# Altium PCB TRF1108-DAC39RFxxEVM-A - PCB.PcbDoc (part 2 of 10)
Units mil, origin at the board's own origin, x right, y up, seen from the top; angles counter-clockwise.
Board outline 4951.22 x 2726.56 mil, 16 copper layers (Top Layer, L2 GND1, L3 PWR1, L4 GND2, L5 PWR2, L6 GND3, L7 Ctrl Signal 1, L8 GND4, L9 GND5, L10 Ctrl Signal 2, L11 GND6, L12 PWR3, L13 GND7, L14 PWR4, L15 GND8, Bottom Layer), stack 80.2 mil thick; 705 components, 433 nets, 3633 pads, 1678 vias.
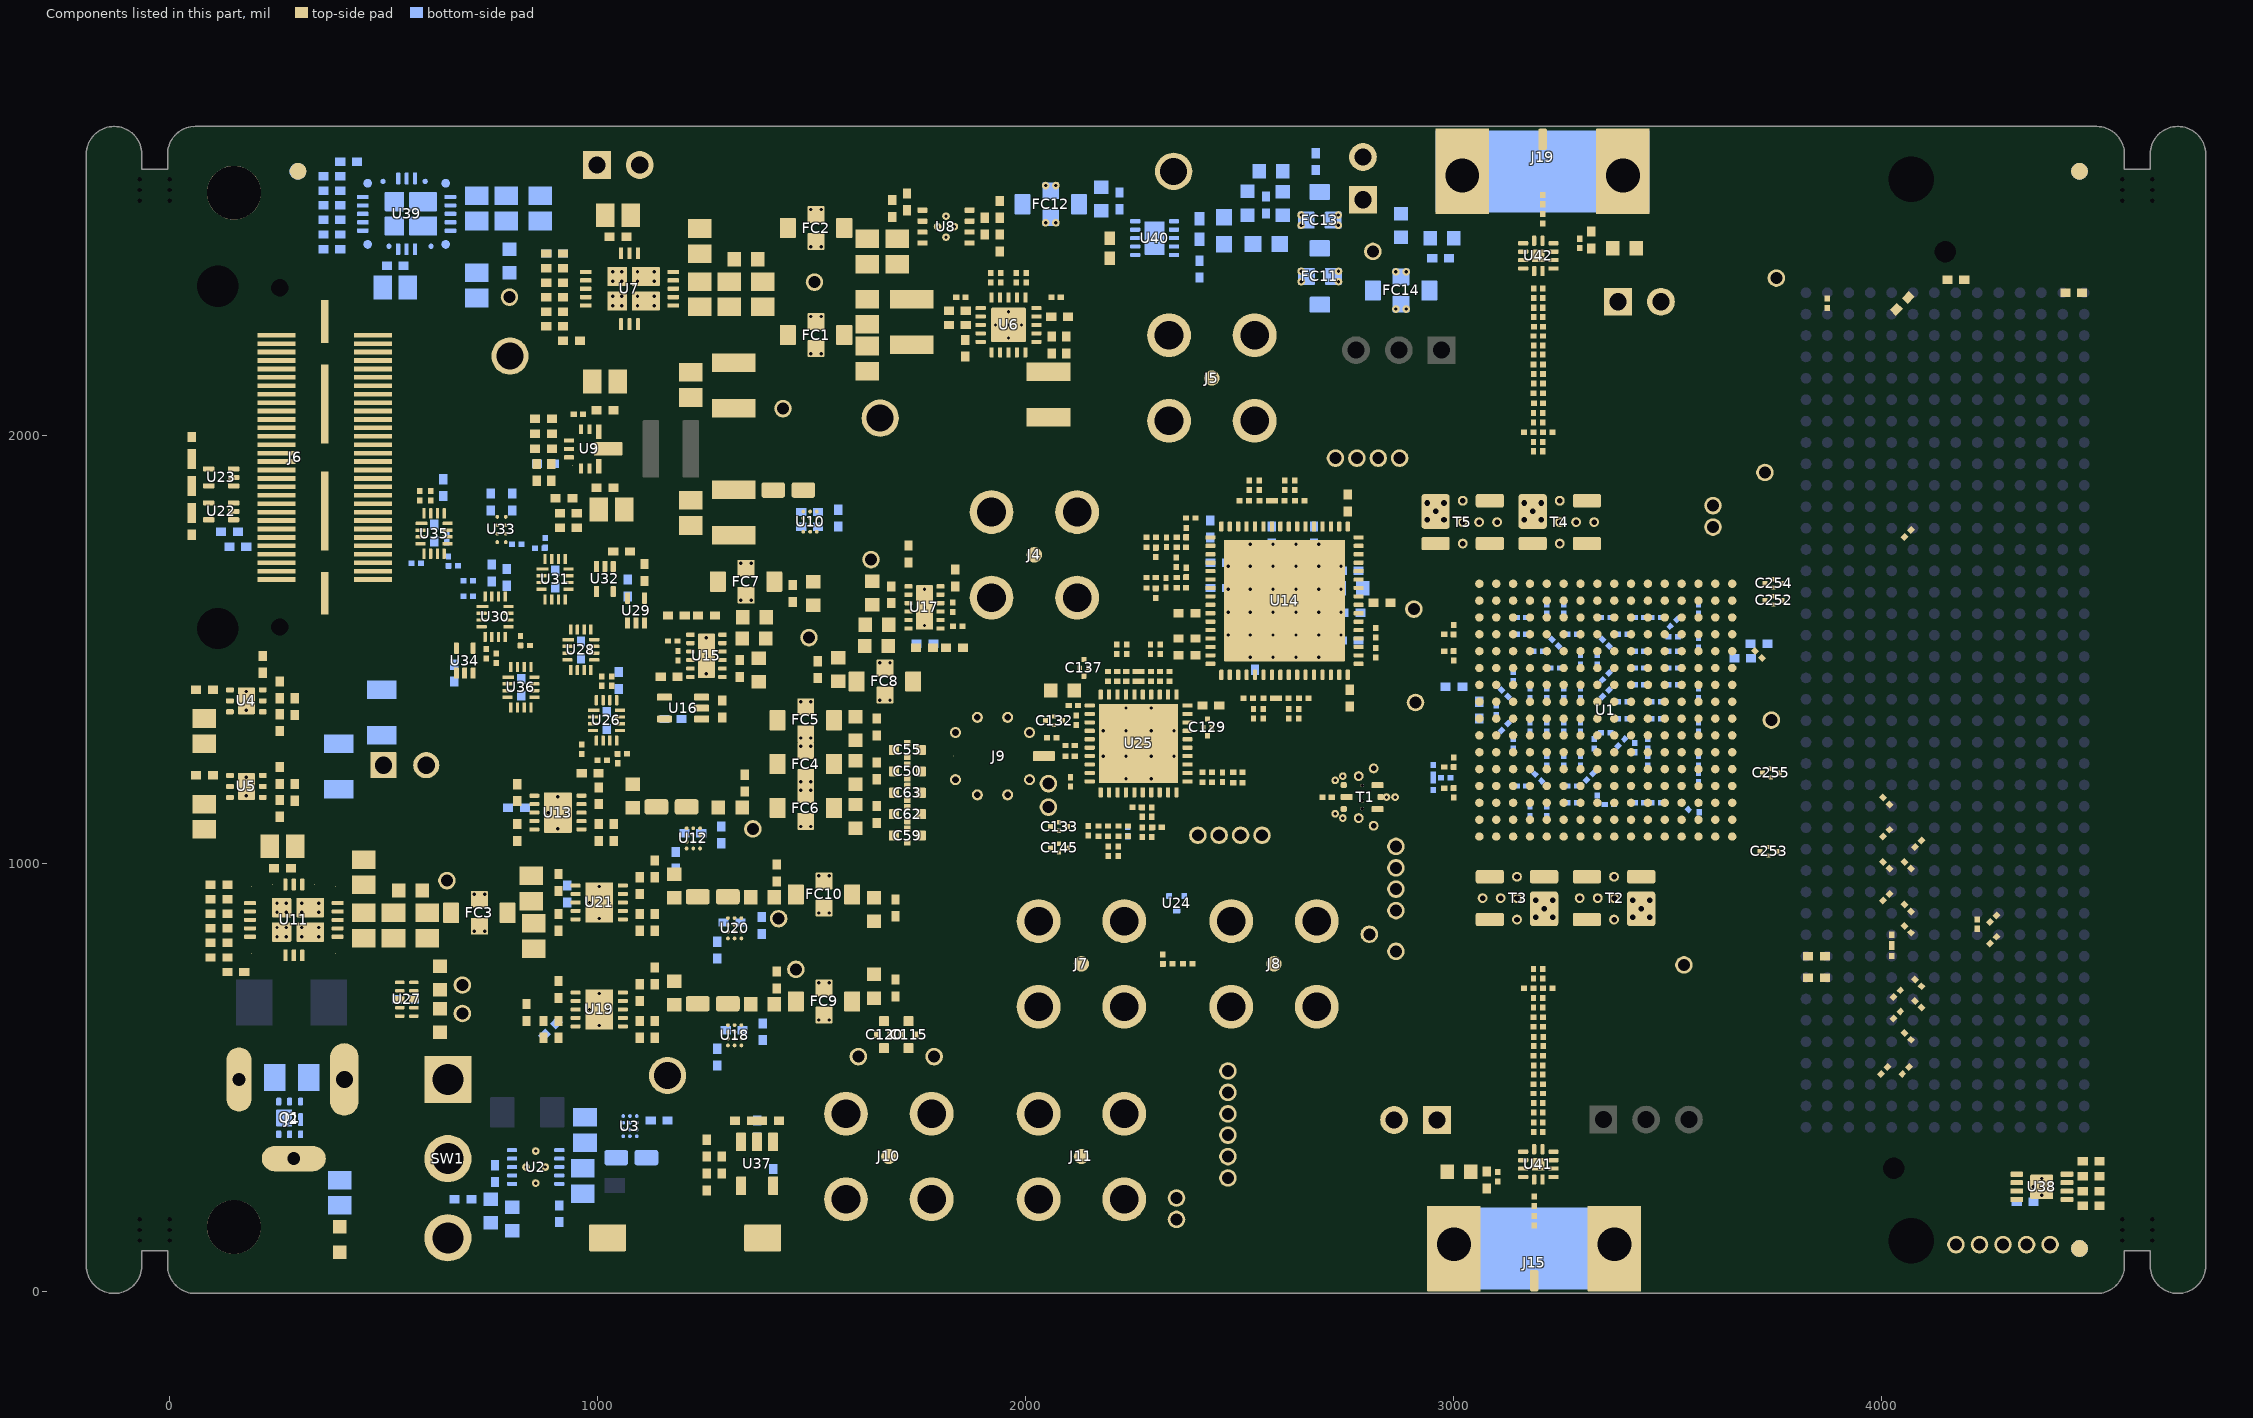
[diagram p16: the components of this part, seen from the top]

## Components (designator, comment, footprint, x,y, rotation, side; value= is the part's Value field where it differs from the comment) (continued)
PP37 "Probe Point" ProbePoint_TH_40mil 2864.85,939.47 r0 top
PP38 "Probe Point" ProbePoint_TH_40mil 2864.85,889.47 r0 top
PP39 "Probe Point" ProbePoint_TH_40mil 3537.64,762.6 r90 top
PP40 "Probe Point" ProbePoint_TH_40mil 3726.83,1913.06 r90 top
PP41 "Probe Point" ProbePoint_TH_40mil 2864.85,794.47 r0 top
PP42 "Probe Point" ProbePoint_TH_40mil 4338.12,109 r90 top
PP43 "Probe Point" ProbePoint_TH_40mil 4283.12,109 r90 top
PP44 "Probe Point" ProbePoint_TH_40mil 4228.12,109 r90 top
PP45 "Probe Point" ProbePoint_TH_40mil 4173.12,109 r90 top
PP46 "Probe Point" ProbePoint_TH_40mil 2352.17,218 r0 top
PP47 "Probe Point" ProbePoint_TH_40mil 2352.17,168 r0 top
PP48 "Probe Point" ProbePoint_TH_40mil 3753.4,2367.25 r0 top
PP49 "Probe Point" ProbePoint_TH_40mil 4393.12,109 r90 top
PP50 "Probe Point" ProbePoint_TH_40mil 793.81,2322.63 r0 bottom
PP51 "Probe Point" ProbePoint_TH_40mil 2810.83,2429.53 r90 top
Q1 "CSD15571Q2" DQK0006C 280.32,405.04 r270 bottom value=20V
R1 "CSS0603FT2L00" CCS0603FLxLxx 1078.28,312.22 r180 bottom value="2 mΩ"
R2 "ERJ-2RKF1004X" 0402L 760,274.77 r90 bottom value="1 MΩ"
R3 "ERJ-2RKF4532X" 0402L 910.24,181.26 r90 bottom value="45.3 kΩ"
R4 "ERJ-2GEJ472X" 0402L 685.43,215 r0 bottom value="4.7 kΩ"
R5 "ERJ-6ENF2201V" 0805L 397.23,230.16 r270 bottom value="2.2 kΩ"
R6 "RCA12060000ZSEA" 1206L 395.4,1226.06 r270 bottom value="0 Ω"
R7 "RCA12060000ZSEA" 1206L 495.4,1352.36 r90 bottom value="0 Ω"
R8 "ERJ-2GEJ472X" 0402L 217.6,1464.88 r90 top value="4.7 kΩ"
R9 "ERJ-2GEJ472X" 0402L 81.15,1405.2 r180 top value="4.7 kΩ"
R10 "ERJ-2GEJ205X" 0402L 292.6,1365.83 r270 top value="2 MΩ"
R11 "ERJ-2GEJ472X" 0402L 81.15,1205.2 r180 top value="4.7 kΩ"
R12 "ERJ-2GEJ365X" 0402L 292.6,1165.83 r270 top value="3.6 MΩ"
R13 "ERJ-2GEJ125X" 0402L 257.6,1405.2 r270 top value="1.2 MΩ"
R14 "ERJ-2GEJ125X" 0402L 257.6,1205.2 r270 top value="1.2 MΩ"
R15 "ERJ-2GEJ472X" 0402L 2079.32,2277.36 r0 top value="4.7 kΩ"
R16 "ERJ-2GEJ104X" 0402L 1840.03,2291.36 r180 top value="100 kΩ"
R17 "ERJ-2GEJ472X" 0402L 1858.91,2203.31 r270 top value="4.7 kΩ"
R18 "ERJ-2GE0R00X" 0402L 2060.43,2211.15 r270 top value="0 Ω"
R19 "ERJ-1GN0R00C" 0201 1848.69,2322.05 r0 top value="0 Ω"
R20 "ERJ-2GEJ472X" 0402L 899.32,2424.63 r180 top value="4.7 kΩ"
R21 "ERJ-1GN0R00C" 0201 1918.3,2367.68 r270 top value="0 Ω"
R22 "ERJ-1GN0R00C" 0201 1941.99,2367.68 r270 top value="0 Ω"
R23 "ERJ-1GN0R00C" 0201 1977.36,2367.68 r270 top value="0 Ω"
R24 "ERJ-1GN0R00C" 0201 2001.04,2367.68 r270 top value="0 Ω"
R25 "ERJ-2GEJ472X" 0402L 899.32,2254.63 r180 top value="4.7 kΩ"
R26 "ERJ-1GN0R00C" 0201 2070.66,2322.05 r180 top value="0 Ω"
R27 "ERJ-2RKF1822X" 0402L 899.32,2356.63 r180 top value="18.2 kΩ"
R28 "ERJ-2GEJ472X" 0402L 938.69,2220.63 r180 top value="4.7 kΩ"
R29 "ERJ-2RKF1822X" 0402L 899.32,2288.63 r0 top value="18.2 kΩ"
R30 "ERJ-2RKF4871X" 0402L 899.32,2322.63 r0 top value="4.87 kΩ"
R31 "ERJ-2GEJ472X" 0402L 1722.49,2545.47 r90 top value="4.7 kΩ"
R32 "ERJ-2RKF3092X" 0402L 1904.53,2488.58 r270 top value="30.9 kΩ"
R33 "ERJ-H2RF1002X" 0402L 1939.53,2527.95 r270 top value="10 kΩ"
R34 "ERJ-2GEJ472X" 0402L 873.22,1968.19 r180 top value="4.7 kΩ"
R35 "ERJ-2GEJ472X" 0402L 931.27,1817.43 r180 top value="4.7 kΩ"
R36 "CSS0603FT2L00" CCS0603FLxLxx 1444.92,1871.8 r180 top value="2 mΩ"
R37 "ERJ-2GE0R00X" 0402L 1495.04,1786.68 r180 bottom value="0 Ω"
R38 "ERJ-2GE0R00X" 0402L 1495.04,1820.68 r180 bottom value="0 Ω"
R39 "ERJ-2GEJ472X" 0402L 931.27,1783.43 r0 top value="4.7 kΩ"
R40 "ERJ-H2RF1002X" 0402L 857.91,1913.5 r270 top value="10 kΩ"
R41 "ERJ-2RKF4871X" 0402L 873.22,2003.19 r0 top value="4.87 kΩ"
R42 "ERJ-2RKF1742X" 0402L 873.22,2038.19 r0 top value="17.4 kΩ"
R43 "ERJ-2GE0R00X" 0402L 877.59,1933.19 r0 bottom value="0 Ω"
R44 "ERJ-H2RF1002X" 0402L 891.91,1913.5 r90 top value="10 kΩ"
R45 "ERJ-H2RF1002X" 0402L 3713.03,1512.58 r0 bottom value="10 kΩ"
R46 "ERJ-1GN0R00C" 0201 3711.83,1487.79 r135 top value="0 Ω"
R47 "ERJ-H2RF1002X" 0402L 3675.04,1478.58 r0 bottom value="10 kΩ"
R48 "ERJ-2GEJ472X" 0402L 115.08,949.98 r180 top value="4.7 kΩ"
R49 "ERJ-2GEJ472X" 0402L 115.08,779.98 r180 top value="4.7 kΩ"
R50 "ERJ-2RKF9311X" 0402L 115.08,881.98 r180 top value="9.31 kΩ"
R51 "ERJ-2GEJ472X" 0402L 154.45,745.98 r180 top value="4.7 kΩ"
R52 "ERJ-2RKF5232X" 0402L 115.08,813.98 r0 top value="52.3 kΩ"
R53 "ERJ-2RKF4871X" 0402L 115.08,847.98 r0 top value="4.87 kΩ"
R54 "ERJ-2GE0R00X" 0402L 1182.58,1007.04 r90 bottom value="0 Ω"
R55 "ERJ-2GE0R00X" 0402L 1222.26,1069.73 r180 bottom value="0 Ω"
R56 "ERJ-H2RF1002X" 0402L 811.87,1072.01 r270 top value="10 kΩ"
R57 "CSS0603FT2L00" CCS0603FLxLxx 1172.15,1131.85 r180 top value="2 mΩ"
R58 "ERJ-2GEJ472X" 0402L 810.32,1130 r180 bottom value="4.7 kΩ"
R59 "ERJ-2RKF8872X" 0402L 1002.11,1157.83 r270 top value="88.7 kΩ"
R60 "ERJ-2RKF1242X" 0402L 982.42,1210.55 r0 top value="12.4 kΩ"
R61 "ERJ-U2RD1202X" 0402L 1002.11,1072.01 r90 top value="12 kΩ"
R62 "ERJ-1GNF49R9C" 0201 2351.78,1703.45 r270 top value="49.9 Ω"
R63 "ERJ-1GN0R00C" 0201 2292.66,1667.59 r0 top value="0 Ω"
R64 "ERJ-1GNF1000C" 0201 2327.69,1655.73 r90 top value="100 Ω"
R65 "ERJ-1GN0R00C" 0201 2292.66,1643.12 r0 top value="0 Ω"
R66 "ERJ-1GNF49R9C" 0201 2303.69,1631.31 r90 top value="49.9 Ω"
R67 "ERJ-1GNF49R9C" 0201 2385.76,1806.69 r180 top value="49.9 Ω"
R68 "ERJ-1GN0R00C" 0201 2292.76,1761.65 r0 top value="0 Ω"
R69 "ERJ-1GNF1000C" 0201 2328.79,1749.78 r90 top value="100 Ω"
R70 "ERJ-1GN0R00C" 0201 2292.76,1737.96 r0 top value="0 Ω"
R71 "ERJ-1GNF49R9C" 0201 2303.79,1726.15 r90 top value="49.9 Ω"
R72 "ERJ-1GNF1200C" 0201 2817.76,1491.9 r90 top value="120 Ω"
R73 "ERJ-1GNF1200C" 0201 2817.76,1538.63 r270 top value="120 Ω"
R74 "ERJ-1GNF1200C" 0201 2520.16,1385.46 r0 top value="120 Ω"
R75 "ERJ-1GNF1200C" 0201 2566.74,1385.46 r180 top value="120 Ω"
R76 "ERJ-1GNF1200C" 0201 2602.96,1385.46 r0 top value="120 Ω"
R77 "ERJ-1GNF1200C" 0201 2649.53,1385.46 r180 top value="120 Ω"
R78 "ERJ-1GNF1200C" 0201 2639.92,1846.92 r180 top value="120 Ω"
R79 "ERJ-1GNF1200C" 0201 2593.11,1846.92 r0 top value="120 Ω"
R80 "ERJ-1GNF1200C" 0201 2556.89,1846.92 r180 top value="120 Ω"
R81 "ERJ-1GNF1200C" 0201 2510.09,1846.92 r0 top value="120 Ω"
R82 "ERJ-H2RF1002X" 0402L 2758.02,1520.52 r0 bottom value="10 kΩ"
R83 "ERJ-H2RF1002X" 0402L 2761.92,1585.21 r0 bottom value="10 kΩ"
R84 "ERJ-2GEJ472X" 0402L 1291.37,1360.2 r270 top value="4.7 kΩ"
R85 "ERJ-2RKF2553X" 0402L 1253.96,1578.94 r0 top value="255 kΩ"
R86 "ERJ-2GEJ472X" 0402L 1166.88,1435.51 r0 top value="4.7 kΩ"
R87 "ERJ-2RKF4993X" 0402L 1183.59,1578.94 r0 top value="499 kΩ"
R88 "ERJ-2GEJ472X" 0402L 1725.98,1722.42 r90 top value="4.7 kΩ"
R89 "ERJ-2GEJ472X" 0402L 1764.69,1512.73 r180 bottom value="4.7 kΩ"
R90 "ERJ-2RKF2553X" 0402L 1763.39,1503.68 r180 top value="255 kΩ"
R91 "ERJ-2GEJ472X" 0402L 1834.79,1666.79 r270 top value="4.7 kΩ"
R92 "ERJ-2RKF4993X" 0402L 1833.76,1503.68 r180 top value="499 kΩ"
R93 "ERJ-2GE0R00X" 0402L 1279.08,547.04 r90 bottom value="0 Ω"
R94 "ERJ-2GE0R00X" 0402L 1318.76,609.73 r180 bottom value="0 Ω"
R95 "ERJ-H2RF1002X" 0402L 908.37,612.01 r270 top value="10 kΩ"
R96 "CSS0603FT20L0" CCS0603FLxLxx 1268.65,671.85 r180 top value="20 mΩ"
R97 "ERJ-2GEJ472X" 0402L 833.53,651.38 r90 top value="4.7 kΩ"
R98 "ERJ-2RKF1153X" 0402L 1098.61,697.83 r270 top value="115 kΩ"
R99 "ERJ-2RKF3302X" 0402L 1133.61,737.2 r270 top value="33 kΩ"
R100 "ERJ-2RKF6651X" 0402L 1098.61,612.01 r90 top value="6.65 kΩ"
R101 "ERJ-2GE0R00X" 0402L 1279.08,797.04 r90 bottom value="0 Ω"
R102 "ERJ-2GE0R00X" 0402L 1313.76,861.73 r180 bottom value="0 Ω"
R103 "ERJ-2GE0R00X" 0402L 873.37,612.01 r90 top value="0 Ω"
R104 "ERJ-H2RF1002X" 0402L 908.37,862.01 r270 top value="10 kΩ"
R105 "CSS0603FT20L0" CCS0603FLxLxx 1268.65,921.85 r180 top value="20 mΩ"
R106 "ERJ-2GEJ472X" 0402L 928.37,928.15 r90 bottom value="4.7 kΩ"
R107 "ERJ-2GE0R00X" 0402L 889.45,612.77 r225 bottom value="0 Ω"
R108 "ERJ-2RKF1153X" 0402L 1098.61,947.83 r270 top value="115 kΩ"
R109 "ERJ-2RKF3302X" 0402L 1133.61,987.2 r270 top value="33 kΩ"
R110 "ERJ-2RKF6651X" 0402L 1098.61,862.01 r90 top value="6.65 kΩ"
R111 "ERJ-2GEJ472X" 0402L 139.69,1775 r180 bottom value="4.7 kΩ"
R112 "ERJ-2GEJ472X" 0402L 51.14,1850.18 r270 top value="4.7 kΩ"
R113 "ERJ-2GE0R00X" 0402L 51.14,1787.31 r270 top value="0 Ω"
R114 "ERJ-2GEJ472X" 0402L 159.11,1740 r0 bottom value="4.7 kΩ"
R115 "ERJ-2GEJ472X" 0402L 51.14,1913.05 r90 top value="4.7 kΩ"
R116 "ERJ-2GE0R00X" 0402L 51.14,1975.92 r90 top value="0 Ω"
R117 "ERJ-1GNF66R5C" 0201 2952,1218.42 r90 bottom value="66.5 Ω"
R118 "ERJ-1GNF66R5C" 0201 2952,1182.2 r90 bottom value="66.5 Ω"
R119 "ERJ-1GN0R00C" 0201 2423.78,1189.41 r0 top value="0 Ω"
R120 "ERJ-1GN0R00C" 0201 2271.75,1072.75 r90 top value="0 Ω"
R121 "ERJ-1GN0R00C" 0201 2423.78,1213.09 r0 top value="0 Ω"
R122 "ERJ-1GNF1000C" 0201 2459.74,1201.25 r90 top value="100 Ω"
R123 "ERJ-1GNF1000C" 0201 2118,1334 r270 top value="100 Ω"
R124 "ERJ-1GN0R00C" 0201 2294.8,1072.75 r90 top value="0 Ω"
R125 "ERJ-1GNF49R9C" 0201 2306.61,1083.77 r180 top value="49.9 Ω"
R126 "ERJ-1GNF49R9C" 0201 2060.34,1293.15 r0 top value="49.9 Ω"
R127 "ERJ-1GNF82R5C" 0201 2181.42,1087.18 r180 top value="82.5 Ω"
R128 "ERJ-1GNF1000C" 0201 2104.41,1190.07 r270 top value="100 Ω"
R129 "ERJ-1GNF49R9C" 0201 2202.7,1448.17 r0 top value="49.9 Ω"
R130 "ERJ-1GNF49R9C" 0201 2245.73,1448.17 r180 top value="49.9 Ω"
R131 "ERJ-1GNF49R9C" 0201 2281.44,1448.17 r0 top value="49.9 Ω"
R132 "ERJ-1GNF49R9C" 0201 2324.47,1448.17 r180 top value="49.9 Ω"
R133 "ERJ-1GN0R00C" 0201 2193.01,1028.16 r90 top value="0 Ω"
R134 "ERJ-1GNF1300C" 0201 2181.42,1063.18 r0 top value="130 Ω"
R135 "ERJ-1GNF82R5C" 0201 2227.64,1087.18 r0 top value="82.5 Ω"
R136 "ERJ-1GN0R00C" 0201 2216.06,1028.16 r90 top value="0 Ω"
R137 "ERJ-1GNF1300C" 0201 2227.64,1063.18 r180 top value="130 Ω"
R138 "ERJ-1GNF49R9C" 0201 2202.7,1425.17 r180 top value="49.9 Ω"
R139 "ERJ-1GNF49R9C" 0201 2245.73,1425.17 r0 top value="49.9 Ω"
R140 "ERJ-1GNF49R9C" 0201 2281.44,1425.17 r180 top value="49.9 Ω"
R141 "ERJ-1GNF49R9C" 0201 2324.47,1425.17 r0 top value="49.9 Ω"
R142 "ERJ-1GN0R00C" 0201 1032.8,1425.8 r270 top value="0 Ω"
R143 "ERJ-1GN0R00C" 0201 1009.23,1425.8 r270 top value="0 Ω"
R144 "ERJ-1GN0R00C" 0201 962.74,1266.32 r90 top value="0 Ω"
R145 "ERJ-1GN0R00C" 0201 1010.18,1241.1 r0 top value="0 Ω"
R146 "ERJ-1GN0R00C" 0201 1057.44,1255.72 r0 top value="0 Ω"
R147 "ERJ-1GN0R00C" 0201 1046.42,1244.7 r90 top value="0 Ω"
R148 "ERJ-3GEYJ222V" 0603L 631.56,731.88 r270 top value="2.2 kΩ"
R149 "ERJ-3GEYJ222V" 0603L 631.56,632.77 r90 top value="2.2 kΩ"
R150 "ERJ-2GEJ472X" 0402L 1109.21,1679.17 r90 top value="4.7 kΩ"
R151 "ERJ-2GEJ472X" 0402L 1069.84,1643.19 r90 bottom value="4.7 kΩ"
R152 "ERJ-1GN0R00C" 0201 697.93,1659.91 r0 bottom value="0 Ω"
R153 "ERJ-1GN0R00C" 0201 697.93,1624.17 r0 bottom value="0 Ω"
R154 "ERJ-1GN0R00C" 0201 739.82,1489.65 r270 top value="0 Ω"
R155 "ERJ-1GN0R00C" 0201 762.82,1478.65 r270 top value="0 Ω"
R156 "ERJ-2GEJ472X" 0402L 1056,1728.44 r180 top value="4.7 kΩ"
R157 "ERJ-1GN0R00C" 0201 830.69,1508.72 r0 top value="0 Ω"
R158 "ERJ-1GN0R00C" 0201 819.67,1519.75 r270 top value="0 Ω"
R159 "ERJ-1GN0R00C" 0201 864.55,1736.04 r180 bottom value="0 Ω"
R160 "ERJ-1GN0R00C" 0201 811.05,1745.36 r0 bottom value="0 Ω"
R161 "ERJ-2GEJ472X" 0402L 899.32,2424.63 r180 bottom value="4.7 kΩ"
R162 "ERJ-1GN0R00C" 0201 877.57,1749.06 r270 bottom value="0 Ω"
R163 "ERJ-2GEJ472X" 0402L 664.58,1444.09 r270 bottom value="4.7 kΩ"
R164 "ERJ-1GN0R00C" 0201 609.82,1858.69 r270 top value="0 Ω"
R165 "ERJ-1GN0R00C" 0201 584.08,1858.69 r90 top value="0 Ω"
R166 "ERJ-1GN0R00C" 0201 647,1761.02 r270 bottom value="0 Ω"
R167 "ERJ-1GN0R00C" 0201 576.14,1701.27 r0 bottom value="0 Ω"
R168 "ERJ-1GN0R00C" 0201 662.34,1694.97 r0 bottom value="0 Ω"
R169 "ERJ-1GN0R00C" 0201 651.32,1705.99 r270 bottom value="0 Ω"
R170 "ERJ-2GEJ104X" 0402L 1254.63,334.41 r90 top value="100 kΩ"
R171 "ERJ-2GE0R00X" 0402L 1289.63,295.04 r270 top value="0 Ω"
R172 "ERJ-2GE0R00X" 0402L 1254.63,255.67 r270 top value="0 Ω"
R173 "ERJ-2GE0R00X" 0402L 1403.72,398.96 r0 top value="0 Ω"
R174 "ERJ-2GE0R00X" 0402L 1340.73,398.96 r180 top value="0 Ω"
R175 "ERJ-1GN0R00C" 0201 3453.51,1239.68 r270 bottom value="0 Ω"
R176 "ERJ-2RKF1001X" 0402L 3000.75,1412.79 r180 bottom value="1 kΩ"
R177 "ERJ-2RKF3601X" 0402L 3059.81,1357.79 r90 bottom value="3.6 kΩ"
R178 "ERJ-2GEJ472X" 0402L 378.68,2604.99 r180 bottom value="4.7 kΩ"
R179 "CRCW040228K7FKED" 0402L 378.68,2502.99 r0 bottom value=28.7k
R180 "ERJ-2RKF4871X" 0402L 378.68,2536.99 r0 bottom value="4.87 kΩ"
R181 "ERJ-2GEJ472X" 0402L 418.05,2638.99 r180 bottom value="4.7 kΩ"
R182 "ERJ-2RKF1822X" 0402L 378.68,2570.99 r0 bottom value="18.2 kΩ"
R183 "ERJ-2GEJ472X" 0402L 378.68,2434.99 r180 bottom value="4.7 kΩ"
R184 "RC0603FR-0710K5L" 0603 2462.67,2477.9 r90 bottom value=10.5k
R185 "RC0603FR-072KL" 0603 2562.03,2446.9 r0 bottom value=2.00k
R186 "ERJ-1GN0R00C" 0201 3187.76,164.84 r270 top value="0 Ω"
R187 "ERJ-1GN0R00C" 0201 3207.44,2550.73 r90 top value="0 Ω"
R189 "ERJ-2GEJ472X" 0402L 2405.95,2388.04 r270 bottom value="4.7 kΩ"
R192 "ERJ-1GNF1400C" 0201 3219.26,708.12 r0 top value="140 Ω"
R196 "RC0201FR-078R66L" 0201 3208.23,741.92 r270 top value="8.66 Ω"
R197 "RC0201FR-078R66L" 0201 3208.23,674.31 r270 top value="8.66 Ω"
R200 "ERJ-1GN0R00C" 0201 3208.23,383.47 r270 top value="0 Ω"
R201 "RC0201FR-078R66L" 0201 3186.18,741.92 r270 top value="8.66 Ω"
R202 "RC0201FR-078R66L" 0201 3186.18,674.31 r270 top value="8.66 Ω"
R204 "ERJ-2GE0R00X" 0402L 4172.81,2363.06 r0 top value="0 Ω"
R205 "ERJ-1GN0R00C" 0201 4260.31,870.56 r45 top value="0 Ω"
R206 "ERJ-1GN0R00C" 0201 4222.81,858.06 r90 top value="0 Ω"
R207 "ERJ-1GN0R00C" 0201 4260.31,820.56 r45 top value="0 Ω"
R208 "ERJ-2GEJ101X" 0402L 4047.78,2308.02 r225 top value="100 Ω"
R209 "ERJ-1GN0R00C" 0201 4060.31,1770.56 r45 top value="0 Ω"
R210 "ERJ-2GEJ472X" 0402L 4489.17,303.88 r0 top value="4.7 kΩ"
R211 "ERJ-1GN0R00C" 0201 4010.31,1145.55 r315 top value="0 Ω"
R212 "ERJ-1GN0R00C" 0201 4010.31,1070.56 r45 top value="0 Ω"
R213 "ERJ-2GEJ472X" 0402L 4489.17,199.51 r180 top value="4.7 kΩ"
R214 "ERJ-2GEJ472X" 0402L 4489.17,234.2 r180 top value="4.7 kΩ"
R215 "ERJ-2GEJ472X" 0402L 4489.17,268.88 r180 top value="4.7 kΩ"
R216 "ERJ-1GN0R00C" 0201 4085.31,1045.56 r225 top value="0 Ω"
R217 "ERJ-1GN0R00C" 0201 4010.31,995.56 r315 top value="0 Ω"
R218 "ERJ-1GN0R00C" 0201 4060.31,995.56 r315 top value="0 Ω"
R219 "ERJ-1GN0R00C" 0201 4010.31,920.56 r45 top value="0 Ω"
R220 "ERJ-1GN0R00C" 0201 4060.31,895.56 r315 top value="0 Ω"
R221 "ERJ-1GN0R00C" 0201 4022.81,822.03 r90 top value="0 Ω"
R222 "ERJ-1GN0R00C" 0201 4060.31,845.56 r315 top value="0 Ω"
R223 "ERJ-1GN0R00C" 0201 4022.81,794.08 r270 top value="0 Ω"
R224 "ERJ-1GN0R00C" 0201 4085.31,720.56 r135 top value="0 Ω"
R225 "ERJ-1GN0R00C" 0201 4035.33,695.56 r225 top value="0 Ω"
R226 "ERJ-1GN0R00C" 0201 4085.31,670.56 r135 top value="0 Ω"
R227 "ERJ-1GN0R00C" 0201 4035.31,645.56 r225 top value="0 Ω"
R228 "ERJ-1GN0R00C" 0201 4060.31,595.56 r315 top value="0 Ω"
R229 "ERJ-1GN0R00C" 0201 4005.61,515.85 r45 top value="0 Ω"
R230 "ERJ-1GN0R00C" 0201 4055.61,515.85 r45 top value="0 Ω"
R231 "ERJ-1GN0R00C" 0201 3872.81,2308.06 r90 top value="0 Ω"
R232 "ERJ-2GEJ101X" 0402L 3847.22,783.06 r0 top value="100 Ω"
R233 "ERJ-2GEJ101X" 0402L 3847.22,733.06 r0 top value="100 Ω"
R234 "ERJ-2GEJ101X" 0402L 4448.4,2333.06 r180 top value="100 Ω"
R236 "ERJ-1GN0R00C" 0201 3186.97,383.47 r270 top value="0 Ω"
R237 "ERJ-1GNF1400C" 0201 3175.16,708.12 r0 top value="140 Ω"
R242 "ERJ-1GNF1400C" 0201 3219.26,2007.46 r0 top value="140 Ω"
R246 "RC0201FR-078R66L" 0201 3208.23,1973.66 r90 top value="8.66 Ω"
R247 "RC0201FR-078R66L" 0201 3208.23,2041.26 r90 top value="8.66 Ω"
R250 "ERJ-1GN0R00C" 0201 3208.23,2332.1 r90 top value="0 Ω"
R251 "RC0201FR-078R66L" 0201 3186.18,1973.66 r90 top value="8.66 Ω"
R252 "RC0201FR-078R66L" 0201 3186.18,2041.26 r90 top value="8.66 Ω"
R255 "ERJ-1GN0R00C" 0201 3186.97,2332.1 r90 top value="0 Ω"
R256 "ERJ-1GNF1400C" 0201 3175.16,2007.46 r0 top value="140 Ω"
SH-J13 "60900213421" Wurth_60900213421 3399,400 r0 top
SH-J14 "60900213421" Wurth_60900213421 2912,401 r0 top
SH-J17 "60900213421" Wurth_60900213421 2921.57,2197.5 r0 top
SH-J18 "60900213421" Wurth_60900213421 3434,2311 r0 top
SW1 "1101M2S3CGE2" FP-1101M2S3CGE2_SIP3-MFG 650,310 r0 top
SW2 "FSMSM" FSMSM 1204.33,124.96 r180 top
T1 "NCR2-123+" NCR2-113+ 2785.8,1154.69 r270 top
T2 "TCBT-123+" TCBT123 3374.37,918.59 r270 top
T3 "TCBT-123+" TCBT123 3147.6,918.59 r270 top
T4 "TCBT-123+" TCBT123 3247.6,1796.99 r90 top
T5 "TCBT-123+" TCBT123 3020.83,1796.99 r90 top
TP1 "5011" Keystone5011 795,2185 r0 top
TP2 "5011" Keystone5011 1660,2040 r0 top
TP3 "5011" Keystone5011 2345.6,2616.53 r90 top
TP4 "5010" Keystone5010 1163.13,504.25 r0 top
U1 "DAC39RF10ACK" ACK0256A 3355.08,1357.79 r180 top
U2 "TPS259261DRC" DRC0010J 855.12,290.32 r0 bottom
U3 "INA231AIYFFR" YFF0012AKAD 1075.34,385.85 r180 bottom
U4 "TPS7A2501DRVR" DRV0006A 179.22,1379.61 r180 top
U5 "TPS7A2501DRVR" DRV0006A 179.22,1179.61 r180 top
U6 "TPS7A8300ARGR" RGR0020A 1959.67,2257.68 r180 top
U7 "TPSM82913RDUR" RDU0028A 1074.19,2342.32 r90 top
U8 "TPS7A8001DRB" DRB0008A 1813.61,2487.4 r180 top
U9 "TPS543620RPYR" RPY0014A 988.52,1968.19 r0 top
U10 "INA231AIYFFR" YFF0012AKAD 1496.1,1798.18 r180 top
U11 "TPSM82913RDUR" RDU0028A 289.95,867.68 r90 top
U12 "INA231AIYFFR" YFF0012AKAD 1223.33,1058.23 r180 top
U13 "TPS7A9401DSC" DSC0010 906.99,1118.46 r0 top
U14 "LMK04828BISQ/NOPB" NKD0064A 2604.53,1613.69 r180 top
U15 "LM27762DSS" DSS0012B 1253.96,1484.72 r180 top
U16 "SN74AUP1G04DCK" DCK0005A 1199.28,1362.69 r180 top
U17 "LM27762DSS" DSS0012B 1763.39,1597.9 r0 top
U18 "INA231AIYFFR" YFF0012AKAD 1319.83,598.23 r180 top
U19 "TPS7A9401DSC" DSC0010 1003.49,658.46 r0 top
U20 "INA231AIYFFR" YFF0012AKAD 1319.83,848.23 r180 top
U21 "TPS7A9401DSC" DSC0010 1003.49,908.46 r0 top
U22 "SN74AUP1G125DRL" DRL0005A 120.28,1822.24 r180 top
U23 "SN74AUP1G125DRL" DRL0005A 120.28,1901.61 r180 top
U24 "PS1608GT2-R50-T1" PS1608G 2352.58,906.78 r0 bottom
U25 "LMX1204RHAT" RHA0040C 2263.59,1279.99 r90 top
U26 "SN74AVC4T774RSV" RSV0016A 1020.44,1333.79 r0 top
U27 "TMUX1136DQA" DQA0010A 554.13,682.32 r0 top
U28 "SN74CBTLV3257RSV" RSV0016A 960.44,1498.79 r0 top
U29 "SN74AUP1G125DRL" DRL0005A 1089.53,1590.35 r90 top
U30 "SN74AVC4T774RSV" RSV0016A 760.44,1576.29 r0 top
U31 "SN74CBTLV3257RSV" RSV0016A 900.44,1663.79 r0 top
U32 "SN74AUP1G125DRL" DRL0005A 1016.63,1664.3 r270 top
U33 "SN74AVC2T45YZP" YZP0008ADAD 775.18,1779.88 r0 top
U34 "SN74AUP1G125DRL" DRL0005A 689.26,1473.54 r90 top
U35 "SN74AVC4T774RSV" RSV0016A 617.7,1770.43 r0 top
U36 "SN74CBTLV3257RSV" RSV0016A 820.44,1411.29 r0 top
U37 "TPS3125J18DBV" DBV0005A 1372.23,297.78 r270 top
U38 "24LC64FT-I/MNY" TDFN8 4373.43,244.04 r180 top
U39 "TPSM82912RDUR" RDU0028A-MFG 553.54,2517.3 r270 bottom
U40 "TPS7A9201DSKR" DSK0010A 2301.04,2460.58 r180 bottom
U41 "TRF1108RPVR" RPV0012A-MFG 3197.6,296.56 r180 top
U42 "TRF1108RPVR" RPV0012A-MFG 3197.6,2419.02 r0 top
ZZ1 "This Assembly Note is for PCB labels only" AssemblyNoteLabel 193.39,3716 r0 top
ZZ2 "These assemblies are ESD sensitive, ESD precautions shall be observed." AssemblyNote 193.39,3866 r0 top
ZZ3 "These assemblies must be clean and free from flux and all contaminants. Use of no clean flux is not acceptable." AssemblyNote 193.39,4015 r0 top
ZZ4 "These assemblies must comply with workmanship standards IPC-A-610 Class 2, unless otherwise specified." AssemblyNote 193.39,4165 r0 top

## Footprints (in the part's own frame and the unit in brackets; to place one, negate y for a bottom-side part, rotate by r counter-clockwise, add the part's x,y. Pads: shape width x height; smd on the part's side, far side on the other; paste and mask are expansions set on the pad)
0201 [mm] "Data from Kemet datasheet CC101_COM dated 7/28/11"
  rect 0.36x0.32 smd mask+0.048: 1(-0.28,0) 2(0.28,0)
  silkscreen extent 0,-0.17 0,0.16, body extent -0.31,-0.16 0.31,0.16, height 0.26
0201_033L [mm] "0201"
  rect 0.36x0.32 smd mask+0.048: 1(-0.28,0) 2(0.28,0)
  body extent -0.31,-0.16 0.31,0.16, height 0.33
0201_cap [mm] "Data from Kemet datasheet CC101_COM dated 7/28/11"
  rect 0.36x0.32 smd mask+0.048: 1(-0.28,0) 2(0.28,0)
  body extent -0.31,-0.16 0.31,0.16, height 0.26
0402 [mm] "0402 from SM-752 data"
  rect 0.8x0.6 smd: 1(-0.6,0) 2(0.6,0)
  silkscreen extent -1.22,-0.52 1.22,0.52, body extent -0.55,-0.3 0.55,0.3, height 0.6
0402_065L [mm] "0402"
  rect 0.6x0.5 smd: 1(-0.5,0) 2(0.5,0)
  body extent -0.55,-0.3 0.55,0.3, height 0.65
0402L [mm] "0402 from SM-752 data"
  rect 0.6x0.5 smd: 1(-0.5,0) 2(0.5,0)
  body extent -0.55,-0.3 0.55,0.3, height 0.6
0402L_cap [mm] "0402 from SM-752 data"
  rect 0.6x0.5 smd: 1(-0.5,0) 2(0.5,0)
  body extent -0.55,-0.3 0.55,0.3, height 0.6
0603 [mm] "0603 from SM-752 data"
  rect 1x0.95 smd: 1(-0.8,0) 2(0.8,0)
  silkscreen extent -1.52,-0.69 1.52,0.69, body extent -0.87,-0.47 0.87,0.47, height 1
0603L [mm] "0603 from SM-752 data"
  rect 0.8x0.85 smd: 1(-0.7,0) 2(0.7,0)
  silkscreen extent -0.07,-0.32 0.07,0.32, body extent -0.87,-0.47 0.87,0.47, height 1
0603L_cap [mm] "0603 from SM-752 data"
  rect 0.8x0.85 smd: 1(-0.7,0) 2(0.7,0)
  silkscreen extent -0.07,-0.33 0.07,0.33, body extent -0.87,-0.47 0.87,0.47, height 1
0805_HV [mil] "0805 with 30mil clearance between pads"
  rect 50x63 smd: 1(-40,0) 2(40,0)
  silkscreen extent -74,-40 74,40, body extent -43,-29 43,29, height 57
0805L [mm] "0805 from SM-752 data"
  rect 1.1x1.4 smd: 1(-0.75,0) 2(0.75,0)
  body extent -1.1,-0.72 1.1,0.72, height 1.45
0805L_cap [mm] "0805 from SM-752 data"
  rect 1.1x1.4 smd: 1(-0.75,0) 2(0.75,0)
  body extent -1.1,-0.72 1.1,0.72, height 1.45
1206L [mm] "1206 from SM-752 data"
  rect 1.1x1.75 smd: 1(-1.35,0) 2(1.35,0)
  silkscreen extent -0.4,-0.77 0.4,0.77, body extent -1.7,-0.9 1.7,0.9, height 1.35
1210L_cap [mm] "1210 from SM-752 data"
  rect 1.1x2.6 smd: 1(-1.35,0) 2(1.35,0)
  silkscreen extent -0.4,-1.2 0.4,1.2, body extent -1.7,-1.35 1.7,1.35, height 1.35
ACK0256A [mm]
  round 0.5 smd paste+0 mask-1000: A1(-7.5,7.5) A2(-6.5,7.5) A3(-5.5,7.5) A4(-4.5,7.5) A5(-3.5,7.5) A6(-2.5,7.5) A7(-1.5,7.5) A8(-0.5,7.5) A9(0.5,7.5) A10(1.5,7.5) A11(2.5,7.5) A12(3.5,7.5) A13(4.5,7.5) A14(5.5,7.5) A15(6.5,7.5) A16(7.5,7.5) B1(-7.5,6.5) B2(-6.5,6.5) B3(-5.5,6.5) B4(-4.5,6.5) B5(-3.5,6.5) B6(-2.5,6.5) B7(-1.5,6.5) B8(-0.5,6.5) B9(0.5,6.5) B10(1.5,6.5) B11(2.5,6.5) B12(3.5,6.5) B13(4.5,6.5) B14(5.5,6.5) B15(6.5,6.5) B16(7.5,6.5) C1(-7.5,5.5) C2(-6.5,5.5) C3(-5.5,5.5) C4(-4.5,5.5) C5(-3.5,5.5) C6(-2.5,5.5) C7(-1.5,5.5) C8(-0.5,5.5) C9(0.5,5.5) C10(1.5,5.5) C11(2.5,5.5) C12(3.5,5.5) C13(4.5,5.5) C14(5.5,5.5) C15(6.5,5.5) C16(7.5,5.5) D1(-7.5,4.5) D2(-6.5,4.5) D3(-5.5,4.5) D4(-4.5,4.5) D5(-3.5,4.5) D6(-2.5,4.5) D7(-1.5,4.5) D8(-0.5,4.5) D9(0.5,4.5) D10(1.5,4.5) D11(2.5,4.5) D12(3.5,4.5) D13(4.5,4.5) D14(5.5,4.5) D15(6.5,4.5) D16(7.5,4.5) E1(-7.5,3.5) E2(-6.5,3.5) E3(-5.5,3.5) E4(-4.5,3.5) E5(-3.5,3.5) E6(-2.5,3.5) E7(-1.5,3.5) E8(-0.5,3.5) E9(0.5,3.5) E10(1.5,3.5) E11(2.5,3.5) E12(3.5,3.5) E13(4.5,3.5) E14(5.5,3.5) E15(6.5,3.5) E16(7.5,3.5) F1(-7.5,2.5) F2(-6.5,2.5) F3(-5.5,2.5) F4(-4.5,2.5) F5(-3.5,2.5) F6(-2.5,2.5) F7(-1.5,2.5) F8(-0.5,2.5) F9(0.5,2.5) F10(1.5,2.5) F11(2.5,2.5) F12(3.5,2.5) F13(4.5,2.5) F14(5.5,2.5) F15(6.5,2.5) F16(7.5,2.5) G1(-7.5,1.5) G2(-6.5,1.5) G3(-5.5,1.5) G4(-4.5,1.5) G5(-3.5,1.5) G6(-2.5,1.5) G7(-1.5,1.5) G8(-0.5,1.5) G9(0.5,1.5) G10(1.5,1.5) G11(2.5,1.5) G12(3.5,1.5) G13(4.5,1.5) G14(5.5,1.5) G15(6.5,1.5) G16(7.5,1.5) H1(-7.5,0.5) H2(-6.5,0.5) H3(-5.5,0.5) H4(-4.5,0.5) H5(-3.5,0.5) H6(-2.5,0.5) H7(-1.5,0.5) H8(-0.5,0.5) H9(0.5,0.5) H10(1.5,0.5) H11(2.5,0.5) H12(3.5,0.5) H13(4.5,0.5) H14(5.5,0.5) H15(6.5,0.5) H16(7.5,0.5) J1(-7.5,-0.5) J2(-6.5,-0.5) J3(-5.5,-0.5) J4(-4.5,-0.5) J5(-3.5,-0.5) J6(-2.5,-0.5) J7(-1.5,-0.5) J8(-0.5,-0.5) J9(0.5,-0.5) J10(1.5,-0.5) J11(2.5,-0.5) J12(3.5,-0.5) J13(4.5,-0.5) J14(5.5,-0.5) J15(6.5,-0.5) J16(7.5,-0.5) K1(-7.5,-1.5) K2(-6.5,-1.5) K3(-5.5,-1.5) K4(-4.5,-1.5) K5(-3.5,-1.5) K6(-2.5,-1.5) K7(-1.5,-1.5) K8(-0.5,-1.5) K9(0.5,-1.5) K10(1.5,-1.5) K11(2.5,-1.5) K12(3.5,-1.5) K13(4.5,-1.5) K14(5.5,-1.5) K15(6.5,-1.5) K16(7.5,-1.5) L1(-7.5,-2.5) L2(-6.5,-2.5) L3(-5.5,-2.5) L4(-4.5,-2.5) L5(-3.5,-2.5) L6(-2.5,-2.5) L7(-1.5,-2.5) L8(-0.5,-2.5) L9(0.5,-2.5) L10(1.5,-2.5) L11(2.5,-2.5) L12(3.5,-2.5) L13(4.5,-2.5) L14(5.5,-2.5) L15(6.5,-2.5) L16(7.5,-2.5) M1(-7.5,-3.5) M2(-6.5,-3.5) M3(-5.5,-3.5) M4(-4.5,-3.5) M5(-3.5,-3.5) M6(-2.5,-3.5) M7(-1.5,-3.5) M8(-0.5,-3.5) M9(0.5,-3.5) M10(1.5,-3.5) M11(2.5,-3.5) M12(3.5,-3.5) M13(4.5,-3.5) M14(5.5,-3.5) M15(6.5,-3.5) M16(7.5,-3.5) N1(-7.5,-4.5) N2(-6.5,-4.5) N3(-5.5,-4.5) N4(-4.5,-4.5) N5(-3.5,-4.5) N6(-2.5,-4.5) N7(-1.5,-4.5) N8(-0.5,-4.5) N9(0.5,-4.5) N10(1.5,-4.5) N11(2.5,-4.5) N12(3.5,-4.5) N13(4.5,-4.5) N14(5.5,-4.5) N15(6.5,-4.5) N16(7.5,-4.5) P1(-7.5,-5.5) P2(-6.5,-5.5) P3(-5.5,-5.5) P4(-4.5,-5.5) P5(-3.5,-5.5) P6(-2.5,-5.5) P7(-1.5,-5.5) P8(-0.5,-5.5) P9(0.5,-5.5) P10(1.5,-5.5) P11(2.5,-5.5) P12(3.5,-5.5) P13(4.5,-5.5) P14(5.5,-5.5) P15(6.5,-5.5) P16(7.5,-5.5) R1(-7.5,-6.5) R2(-6.5,-6.5) R3(-5.5,-6.5) R4(-4.5,-6.5) R5(-3.5,-6.5) R6(-2.5,-6.5) R7(-1.5,-6.5) R8(-0.5,-6.5) R9(0.5,-6.5) R10(1.5,-6.5) R11(2.5,-6.5) R12(3.5,-6.5) R13(4.5,-6.5) R14(5.5,-6.5) R15(6.5,-6.5) R16(7.5,-6.5) T1(-7.5,-7.5) T2(-6.5,-7.5) T3(-5.5,-7.5) T4(-4.5,-7.5) T5(-3.5,-7.5) T6(-2.5,-7.5) T7(-1.5,-7.5) T8(-0.5,-7.5) T9(0.5,-7.5) T10(1.5,-7.5) T11(2.5,-7.5) T12(3.5,-7.5) T13(4.5,-7.5) T14(5.5,-7.5) T15(6.5,-7.5) T16(7.5,-7.5)
  silkscreen extent -9.25,-8.6 8.6,8.6, body extent -9.1,-9.1 9.1,9.1, height 0.25
AssemblyNote [mil] "Assembly Note"
AssemblyNoteLabel [mil] "Assembly Note for PCB Labels"
ATS-54170R-C1-R0_BGA_HEATSINK_17p0x17p0mm [mil]
  body extent -339,-339 339,339, height 10
CAPC0603X28X15LL05T05 [mm] "Chip Capacitor, 2-Leads, Body 0.60x0.33mm, IPC High Density"
  rect 0.36x0.34 smd: 1(-0.28,0) 2(0.28,0)
  body extent -0.32,-0.19 0.33,0.19, height 0.28
CAPC0603X28X15NL05T05 [mm] "Chip Capacitor, 2-Leads, Body 0.60x0.33mm, IPC Medium Density"
  rect 0.36x0.32 smd mask+0.051: 1(-0.28,0) 2(0.28,0)
  body extent -0.32,-0.19 0.33,0.19, height 0.28
CCS0603FLxLxx [mm]
  rrect33% 1.41x0.92 smd: 1(-0.9,0) 2(0.89,0)
  body extent -0.93,-0.52 0.93,0.52, height 0.66
CE_Mark_5mm [mil] "Minimum text height for CE Mark"
  silkscreen extent -138,-98 138,98
Cinch_145-0701-802 [mil] "50 Ohm JACK, SMT"
  rrect37% 19.68x50 smd: 1(0,-25)
  round 100 hole 79: 2(-187.5,-110) 2(187.5,-110)
  rrect2% 125x200 smd: 2(-187.5,-100) 3(187.5,-100)
  rrect2% 500x192 smd far side: 4(0,-100)
  body extent -250,-198 250,551, height 254
DBV0005A [mm] "SOT23, 5-Leads, Body 2.9x1.6mm, Pitch 0.95mm, Lead Span 2.8mm, IPC High Density"
  rrect18% 1.1x0.6 smd mask+0.07: 1(-1.3,0.95) 2(-1.3,0) 3(-1.3,-0.95) 4(1.3,-0.95) 5(1.3,0.95)
  silkscreen extent -0.35,-1.55 0.35,1.55, body extent -1.42,-1.46 1.42,1.46, height 1.09
DCK0005A [mm] "SOT353, 5-Leads, Body 2x1.3mm, Pitch 0.65mm, Lead Span 2.1mm, IPC High Density"
  rrect25% 0.9x0.4 smd mask+0.05: 1(-1.1,0.65) 2(-1.1,0) 3(-1.1,-0.65) 4(1.1,-0.65) 5(1.1,0.65)
  silkscreen extent -0.25,-1.1 0.25,1.1, body extent -1.14,-1 1.14,1, height 0.95
DQA0010A [mm] "SON, 10-Leads, Body 1x2.5mm, Pitch 0.5mm, TI Recommended"
  rrect50% 0.565x0.2 smd mask+0.07: 1(-0.417,1) 2(-0.417,0.5) 4(-0.417,-0.5) 5(-0.417,-1) 6(0.417,-1) 7(0.417,-0.5) 9(0.417,0.5) 10(0.417,1)
  rrect28% 0.565x0.36 on Top Paste mask+0.07: 3(-0.417,0) 8(0.417,0)
  rrect25% 0.565x0.4 smd paste-0.2 mask+0.03: 3(-0.417,0) 8(0.417,0)
  silkscreen extent -0.67,-1.45 0.55,1.45, body extent -0.55,-1.3 0.55,1.3, height 0.56
DQK0006C [mm] "WSON"
  rrect12% 0.9x0.86 on Bottom Paste: 0(0,0.325)
  rrect34% 0.7x0.29 on Bottom Paste: 0(0.095,-0.65)
  rrect33% 0.45x0.3 smd: 1(-0.975,0.65) 2(-0.975,0) 3(-0.975,-0.65) 4(0.975,-0.65) 5(0.975,0) 6(0.975,0.65)
  rrect33% 0.75x0.3 smd paste-0.15: 7(0.095,-0.65)
  rrect11% 1x0.95 smd paste-0.5: 8(0,0.325)
  silkscreen extent -1.15,-1.15 1.15,1.15, body extent -1,-1 1,1, height 0.82
DRB0008A [mm] "VSON-8"
  rrect32% 0.6x0.31 smd mask+0.07: 1(-1.4,0.975) 2(-1.4,0.325) 3(-1.4,-0.325) 4(-1.4,-0.975) 5(1.4,-0.975) 6(1.4,-0.325) 7(1.4,0.325) 8(1.4,0.975)
  round 0.454 hole 0.2 mask+0.05: 9(-0.5,0) 9(0,0.625) 9(0,-0.625) 9(0.5,0)
  round 0.025 smd paste-1.75 mask+0.07: 9(0,0)
  Top Layer region: -0.7,-0.875 -0.49,-0.875 -0.471,-0.879 -0.455,-0.89 -0.444,-0.906 -0.44,-0.925 -0.44,-0.925 -0.44,-1.65 -0.436,-1.669 -0.425,-1.685 -0.409,-1.696 -0.39,-1.7 -0.39,-1.7 -0.26,-1.7 -0.241,-1.696 -0.225,-1.685 -0.214,-1.669 -0.21,-1.65 -0.21,-1.65 -0.21,-0.925 -0.206,-0.906 -0.195,-0.89 -0.179,-0.879 -0.16,-0.875 -0.16,-0.875 0.16,-0.875 0.179,-0.879 0.195,-0.89 0.206,-0.906 0.21,-0.925 0.21,-0.925 0.21,-1.65 0.21,-1.65 0.214,-1.669 0.225,-1.685 0.241,-1.696 0.26,-1.7 0.26,-1.7 0.39,-1.7 0.409,-1.696 0.425,-1.685 0.436,-1.669 0.44,-1.65 0.44,-1.65 0.44,-0.925 0.444,-0.906 0.455,-0.89 0.471,-0.879 0.49,-0.875 0.49,-0.875 0.7,-0.875 0.719,-0.871 0.735,-0.86 0.746,-0.844 0.75,-0.825 0.75,-0.825 0.75,0.825 0.746,0.844 0.735,0.86 0.719,0.871 0.7,0.875 0.7,0.875 0.49,0.875 0.471,0.879 0.455,0.89 0.444,0.906 0.44,0.925 0.44,0.925 0.44,1.65 0.436,1.669 0.425,1.685 0.409,1.696 0.39,1.7 0.39,1.7 0.26,1.7 0.241,1.696 0.225,1.685 0.214,1.669 0.21,1.65 0.21,1.65 0.21,1.65 0.21,0.925 0.206,0.906 0.195,0.89 0.179,0.879 0.16,0.875 0.16,0.875 -0.16,0.875 -0.179,0.879 -0.195,0.89 -0.206,0.906 -0.21,0.925 -0.21,0.925 -0.21,1.65 -0.214,1.669 -0.225,1.685 -0.241,1.696 -0.26,1.7 -0.26,1.7 -0.39,1.7 -0.409,1.696 -0.425,1.685 -0.436,1.669 -0.44,1.65 -0.44,1.65 -0.44,0.925 -0.444,0.906 -0.455,0.89 -0.471,0.879 -0.49,0.875 -0.49,0.875 -0.7,0.875 -0.719,0.871 -0.735,0.86 -0.746,0.844 -0.75,0.825 -0.75,0.825 -0.75,-0.825 -0.746,-0.844 -0.735,-0.86 -0.719,-0.871 -0.7,-0.875
  silkscreen extent -1.73,-1.73 1.73,1.73, body extent -1.5,-1.5 1.5,1.5, height 0.77
DRC0010J [mm] "VSON-10"
  rrect42% 0.6x0.24 smd mask+0.07: 1(-1.4,1) 2(-1.4,0.5) 3(-1.4,0) 4(-1.4,-0.5) 5(-1.4,-1) 6(1.4,-1) 7(1.4,-0.5) 8(1.4,0) 9(1.4,0.5) 10(1.4,1)
  round 0.454 hole 0.2 mask+0.05: 11(-0.575,0) 11(0,-0.95) 11(0,0.95) 11(0.575,0)
  round 0.025 smd mask+0.07: 11(0,0)
  Top Layer region: -0.375,-1.65 -0.375,-1.2 -0.775,-1.2 -0.794,-1.196 -0.81,-1.185 -0.821,-1.169 -0.825,-1.15 -0.825,-1.15 -0.825,1.15 -0.821,1.169 -0.81,1.185 -0.794,1.196 -0.775,1.2 -0.775,1.2 -0.375,1.2 -0.375,1.65 -0.371,1.669 -0.36,1.685 -0.344,1.696 -0.325,1.7 -0.325,1.7 -0.325,1.7 -0.175,1.7 -0.175,1.7 -0.156,1.696 -0.14,1.685 -0.129,1.669 -0.125,1.65 -0.125,1.65 -0.125,1.2 0.125,1.2 0.125,1.65 0.129,1.669 0.14,1.685 0.156,1.696 0.175,1.7 0.175,1.7 0.175,1.7 0.325,1.7 0.325,1.7 0.344,1.696 0.36,1.685 0.371,1.669 0.375,1.65 0.375,1.65 0.375,1.2 0.775,1.2 0.794,1.196 0.81,1.185 0.821,1.169 0.825,1.15 0.825,1.15 0.825,-1.15 0.821,-1.169 0.81,-1.185 0.794,-1.196 0.775,-1.2 0.775,-1.2 0.375,-1.2 0.375,-1.65 0.371,-1.669 0.36,-1.685 0.344,-1.696 0.325,-1.7 0.325,-1.7 0.175,-1.7 0.156,-1.696 0.14,-1.685 0.129,-1.669 0.125,-1.65 0.125,-1.65 0.125,-1.2 -0.125,-1.2 -0.125,-1.65 -0.129,-1.669 -0.14,-1.685 -0.156,-1.696 -0.175,-1.7 -0.175,-1.7 -0.325,-1.7 -0.344,-1.696 -0.36,-1.685 -0.371,-1.669 -0.375,-1.65
  body extent -1.5,-1.5 1.5,1.5, height 1
DRL0005A [mm] "SOTFL, 5-Flat Leads, Body 1.2x1.6x0.6mm, Pitch 0.5mm, TI recommended"
  rrect33% 0.67x0.3 smd mask+0.05: 1(-0.74,0.5) 2(-0.74,0) 3(-0.74,-0.5) 4(0.74,-0.5) 5(0.74,0.5)
  silkscreen extent -0.9,-0.95 0.5,0.95, body extent -0.85,-0.85 0.85,0.85, height 0.62
DRV0006A [mm] "SON, 6-Leads, Body 2x2mm, Pitch 0.65mm, Thermal Pad 1.6x1mm, TI Recommended"
  rrect33% 0.45x0.3 smd mask+0.07: 1(-0.975,0.65) 2(-0.975,0) 3(-0.975,-0.65) 4(0.975,-0.65) 5(0.975,0) 6(0.975,0.65)
  round 0.454 hole 0.2 mask+0: 7(0,0.55) 7(0,-0.55)
  rrect14% 1x0.7 on Top Paste: 7(0,0.45) 7(0,-0.45)
  rrect10% 1x1.6 smd paste-0.5 mask+0.07: 7(0,0)
  silkscreen extent -1.05,-1.2 1.05,1.2, body extent -1.05,-1.05 1.05,1.05, height 0.81
DSC0010 [mm]
  rrect50% 0.6x0.24 smd paste+0 mask+0.07: 1(-1.4,1) 2(-1.4,0.5) 3(-1.4,0) 4(-1.4,-0.5) 5(-1.4,-1) 6(1.4,-1) 7(1.4,-0.5) 8(1.4,0) 9(1.4,0.5) 10(1.4,1)
  round 0.454 hole 0.2 mask+0.05: 11(-0.575,0) 11(0,-0.95) 11(0,0.95) 11(0.575,0)
  rrect6% 1.65x2.4 smd paste-1000 mask+0: 11(0,0)
  silkscreen extent -1.93,-1.55 1.55,1.55, body extent -1.8,-1.8 1.8,1.8, height 0.25
DSK0010A [mm] "SON, 10-Leads, Body 2.5x2.5mm, Pitch 0.5mm, Thermal Pad 2x1.2mm - ADI"
  rrect40% 0.6x0.25 smd: 1(-1.15,1) 2(-1.15,0.5) 3(-1.15,0) 4(-1.15,-0.5) 5(-1.15,-1) 6(1.15,-1) 7(1.15,-0.5) 8(1.15,0) 9(1.15,0.5) 10(1.15,1)
  rrect11% 1.13x0.89 on Bottom Paste: 11(0,-0.545) 11(0,0.545)
  rrect8% 1.2x2 smd paste-0.6: 11(0,0)
  silkscreen extent -1.3,-1.45 1.3,1.45, body extent -1.25,-1.25 1.25,1.25, height 0.8
DSS0012B [mm] "WSON-10"
  rrect40% 0.5x0.25 smd mask+0.05: 1(-0.95,1.25) 2(-0.95,0.75) 3(-0.95,0.25) 4(-0.95,-0.25) 5(-0.95,-0.75) 6(-0.95,-1.25) 7(0.95,-1.25) 8(0.95,-0.75) 9(0.95,-0.25) 10(0.95,0.25) 11(0.95,0.75) 12(0.95,1.25)
  round 0.454 hole 0.2 mask+0.05: 13(0,1.075) 13(0,-1.075) 13(0,0)
  rrect11% 1x2.65 smd paste-0.5 mask+0.05: 13(0,0)
  silkscreen extent -1.3,1.63 -1.24,1.68, body extent -1,-1.5 1,1.5, height 0.81
ESD_Overlay_Medium [mil]
  silkscreen extent -127,-109 125,110
F17HA-05HC_FAN_17p0x17p0mm [mil]
  body extent -348,-348 348,348, height 10
FCC_disclaimer_stacked [mil]
FDL_Small [mil]
  silkscreen extent -54,-32 54,73
Fiducial10-20 [mm]
  round 1 smd mask+0.203: 1(0,0)
FP-1101M2S3CGE2_SIP3-MFG [mm]
  rrect4% 2.8x2.8 hole 1.85 paste-2539.97 mask+0: 1(0,4.7)
  round 2.8 hole 1.85 paste-2539.97 mask+0: 2(0,0) 3(0,-4.7)
  silkscreen extent -3.3,-6.35 3.3,6.35, body extent -3.4,-6.45 3.4,6.45, height 0.25
FP-2116-440-AL_STANDOFF_HEX_1-4-MFG [mm]
  round 3.2 hole 3.2 unplated paste-2539.97 mask+0: ""(0,0)
  body extent -3.66,-3.17 3.66,3.18, height 31.88
FP-132134-15_CONN_SMA_JACK-MFG [mm]
  round 0.914 smd paste+0 mask+0: 1(0,0)
  round 2.6 hole 1.7 paste-2539.97 mask+0: 2(-2.54,2.54) 3(2.54,2.54) 4(-2.54,-2.54) 5(2.54,-2.54)
  silkscreen extent -3.6,-3.6 3.6,3.6, body extent -3.94,-3.94 3.94,3.94, height 0.25
FP-LQP03HQ_02-MFG [mm]
  rect 0.36x0.32 smd paste+0 mask+0.051: 1(-0.27,0) 2(0.27,0)
  body extent -0.55,-0.27 0.55,0.26, height 0.25
FSMSM [mm]
  rrect10% 2.2x1.6 smd: 1(-4.6,0) 2(4.6,0)
  body extent -4.98,-1.75 4.98,1.75, height 4.4
FTDI_Dongle_004 [mm]
  rect 2.27x0.279 smd: 1(18.74,-7.25) 2(13.01,-7.25) 3(18.74,-6.75) 4(13.01,-6.75) 5(18.74,-6.25) 6(13.01,-6.25) 7(18.74,-5.75) 8(13.01,-5.75) 9(18.74,-5.25) 10(13.01,-5.25) 11(18.74,-4.75) 12(13.01,-4.75) 13(18.74,-4.25) 14(13.01,-4.25) 15(18.74,-3.75) 16(13.01,-3.75) 17(18.74,-3.25) 18(13.01,-3.25) 19(18.74,-2.75) 20(13.01,-2.75) 21(18.74,-2.25) 22(13.01,-2.25) 23(18.74,-1.75) 24(13.01,-1.75) 25(18.74,-1.25) 26(13.01,-1.25) 27(18.74,-0.75) 28(13.01,-0.75) 29(18.74,-0.25) 30(13.01,-0.25) 31(18.74,0.25) 32(13.01,0.25) 33(18.74,0.75) 34(13.01,0.75) 35(18.74,1.25) 36(13.01,1.25) 37(18.74,1.75) 38(13.01,1.75) 39(18.74,2.25) 40(13.01,2.25) 41(18.74,2.75) 42(13.01,2.75) 43(18.74,3.25) 44(13.01,3.25) 45(18.74,3.75) 46(13.01,3.75) 47(18.74,4.25) 48(13.01,4.25) 49(18.74,4.75) 50(13.01,4.75) 51(18.74,5.25) 52(13.01,5.25) 53(18.74,5.75) 54(13.01,5.75) 55(18.74,6.25) 56(13.01,6.25) 57(18.74,6.75) 58(13.01,6.75) 59(18.74,7.25) 60(13.01,7.25)
  round 2 hole 2.45 unplated: 4(9.525,-10.16) 4(9.525,10.16)
  round 0 hole 1.02 unplated: MH1(13.205,-10.065) MH2(13.205,10.065)
  rect 0.43x2.54 smd: MP1(15.875,-8.065) MP4(15.875,8.065)
  rect 0.43x4.7 smd: MP2(15.875,-3.175) MP3(15.875,3.175)
  silkscreen extent 12.26,-10.66 19.78,10.65, body extent -22.78,-12.7 22.22,12.7, height 10.54
IEC_HotSurface_Small [mil]
  silkscreen extent -107,-93 107,92
Keystone5010 [mil] "Keystone Multipurpose loops"
  round 87 hole 63: 1(0,0)
  silkscreen extent -70,-70 70,70, body extent -63,-63 63,62, height 319
Keystone5011 [mil] "Keystone Multipurpose loops"
  round 87 hole 63: 1(0,0)
  silkscreen extent -70,-70 70,70, body extent -63,-63 63,62, height 319
Label_650x200 [mil] "Thermal Transfer Label"
  round 1 on Mech13: 0(0,0)
  silkscreen extent -325,-100 325,100, body extent -325,-100 325,100, height 1
LED_LTST-C190-Green [mm] "Lite-On"
  rect 0.8x0.8 smd: 1(-0.75,0) 2(0.75,0)
  silkscreen extent -1.1,-0.8 1.8,0.8, body extent -0.85,-0.45 0.85,0.45, height 0.91
Molex_22-23-2021 [mm] "Header, 2.54mm, 2x1, TH"
  rrect6% 1.55x1.55 hole 1.02: 1(-1.27,0)
  round 1.55 hole 1.02: 2(1.27,0)
  silkscreen extent -2.92,-3.25 2.46,3.1, body extent -2.46,-3.25 2.46,3.1, height 10.08
Molex_0853050232 [mm] "Plug, 50 Ohm, Straight, SMT"
  rrect17% 0.6x1.3 smd: 1(0,0)
  round 0.654 hole 0.4 mask+0.05: 2(-2.3,-2.15) 2(-2.3,-3.95) 2(-1.4,-0.85) 2(-1.4,-5.25) 2(1.4,-0.85) 2(1.4,-5.25) 2(2.3,-2.15) 2(2.3,-3.95)
  round 0.025 smd: 2(0,-5.35)
  Top Layer pour cut-out: 0.998,-1.315 0.998,-0.45 -0.998,-0.45 -0.998,-1.321 -1.679,-1.973 -1.986,-2.865 -1.849,-3.798 -1.3,-4.565 -0.461,-4.995 0.482,-4.992 1.319,-4.557 1.864,-3.787 1.995,-2.854 1.683,-1.963 0.998,-1.315
  Top Layer region: -2.6,-5.65 -2.6,-0.45 -1,-0.45 -1,-1.318 -1.732,-2.05 -2,-3.05 -1.732,-4.05 -1,-4.782 0,-5.05 1,-4.782 1.732,-4.05 2,-3.05 1.732,-2.05 1,-1.318 1,-1.318 1,-0.45 2.6,-0.45 2.6,-5.65
  L2 GND1 pour cut-out: -0.33,0.699 -0.33,-0.698 0.33,-0.698 0.33,0.699
  L2 GND1 pour cut-out: 0.998,-1.315 0.998,-0.45 -0.998,-0.45 -0.998,-1.321 -1.679,-1.973 -1.986,-2.865 -1.849,-3.798 -1.3,-4.565 -0.461,-4.995 0.482,-4.992 1.319,-4.557 1.864,-3.787 1.995,-2.854 1.683,-1.963 0.998,-1.315
  L3 PWR1 pour cut-out: -0.33,0.699 -0.33,-0.698 0.33,-0.698 0.33,0.699
  L3 PWR1 pour cut-out: 0.998,-1.315 0.998,-0.45 -0.998,-0.45 -0.998,-1.321 -1.679,-1.973 -1.986,-2.865 -1.849,-3.798 -1.3,-4.565 -0.461,-4.995 0.482,-4.992 1.319,-4.557 1.864,-3.787 1.995,-2.854 1.683,-1.963 0.998,-1.315
  L3 PWR1 pour cut-out: 0.998,-1.315 0.998,-0.45 -0.998,-0.45 -0.998,-1.321 -1.679,-1.973 -1.986,-2.865 -1.849,-3.798 -1.3,-4.565 -0.461,-4.995 0.482,-4.992 1.319,-4.557 1.864,-3.787 1.995,-2.854 1.683,-1.963 0.998,-1.315
  body extent -2.5,-5.55 2.5,0.45, height 4.1
NCR2-113+ [mil]
  rrect50% 14.17x14.17 smd: 1(-28,-42.91) 3(28,-42.91) 5(0,42.91)
  rrect28% 14x28 smd paste+0: 2(0,-36) 4(-28,36) 6(28,36)
  round 23 hole 13 mask+4: 5(-67,27) 5(-49,-8) 5(49,-8) 5(67,27)
  round 18 hole 8 mask+4: 5(-49,-45) 5(-39,-63) 5(0,77) 5(0,57) 5(39,-63) 5(49,-45)
  round 8 hole 8 mask+1.5: 5(-27,0) 5(-9,0) 5(9,0) 5(27,0)
  Top Layer region: -35,-46.69 -35,4.37 -34.72,5.76 -33.94,6.94 -32.76,7.72 -31.37,8 -31.37,8 -9.72,8 -8.68,8.21 -7.8,8.8 -7.21,9.68 -7,10.72 -7,10.72 -7,46.15 -6.48,48.07 -5.07,49.48 -3.15,50 -3.15,50 3.15,50 4.62,49.71 5.87,48.87 6.71,47.62 7,46.15 7,46.15 7,10.72 7.21,9.68 7.8,8.8 8.68,8.21 9.72,8 9.72,8 32.35,8 33.37,7.8 34.22,7.22 34.8,6.37 35,5.35 35,5.35 35,-46.69 34.75,-47.96 34.03,-49.03 32.96,-49.75 31.69,-50 31.69,-50 24.41,-50 23.1,-49.74 22,-49 21.26,-47.9 21,-46.59 21,-46.59 21,-10.17 20.83,-9.34 20.36,-8.64 19.66,-8.17 18.83,-8 18.83,-8 -18.83,-8 -19.66,-8.17 -20.36,-8.64 -20.84,-9.34 -21,-10.17 -21,-10.17 -21,-46.59 -21.26,-47.9 -22,-49 -23.11,-49.74 -24.41,-50 -24.41,-50 -31.69,-50 -32.96,-49.75 -34.03,-49.03 -34.75,-47.96 -35,-46.69
  body extent -43,-54 43,54, height 10
NFM15PC [mm] "SMD, 3-Leads, Body 1x0.5mm"
  rrect10% 0.3x0.3 smd mask+0.05: 1(-0.5,0) 3(0.5,0)
  rrect10% 0.25x0.25 smd mask+0.05: 2(0,0.25) 2(0,-0.25)
  body extent -0.55,-0.3 0.55,0.3, height 0.35
NFM18PC [mm]
  rrect20% 0.6x0.6 smd mask+0.05: 1(-0.8,0) 3(0.8,0)
  rrect20% 0.4x0.4 smd mask+0.05: 2(0,-0.4) 2(0,0.4)
  body extent -1.28,-0.87 1.28,0.87, height 0.25
NFM31PC#1 [mm]
  rrect10% 0.95x1.2 smd paste+0: 1(-1.675,0) 3(1.675,0)
  round 0.2 hole 0.2 mask+0.05: 2(-0.305,-1.105) 2(-0.305,1.105) 2(0.305,-1.105) 2(0.305,1.105)
  rrect10% 1x1 smd paste+0: 2(0,-0.8) 2(0,0.8)
  body extent -1.7,-0.9 1.7,0.9, height 1.5
NFM31PC#2 [mm]
  rrect10% 0.95x1.2 smd paste+0: 1(-1.675,0) 3(1.675,0)
  round 0.2 hole 0.2 mask+0.05: 2(-0.305,-1.054) 2(-0.305,1.054) 2(0.305,-1.054) 2(0.305,1.054)
  rrect10% 1x1 smd paste+0: 2(0,-0.8) 2(0,0.8)
  body extent -1.7,-0.9 1.7,0.9, height 1.5
NFM31PC#3 [mm]
  rrect10% 0.95x1.2 smd paste+0: 1(-1.675,0) 3(1.675,0)
  round 0.2 hole 0.2 mask+0.05: 2(-0.305,-1.054) 2(-0.305,1.105) 2(0.305,-1.054) 2(0.305,1.105)
  rrect10% 1x1 smd paste+0: 2(0,-0.8) 2(0,0.8)
  body extent -1.7,-0.9 1.7,0.9, height 1.5
NFM31PC#4 [mm]
  rrect10% 0.95x1.2 smd paste+0: 1(-1.675,0) 3(1.675,0)
  round 0.2 hole 0.2 mask+0.05: 2(-0.305,-1.105) 2(-0.305,1.054) 2(0.305,-1.105) 2(0.305,1.054)
  rrect10% 1x1 smd paste+0: 2(0,-0.8) 2(0,0.8)
  body extent -1.7,-0.9 1.7,0.9, height 1.5
NFM31PC#5 [mm]
  rrect10% 0.95x1.2 smd paste+0: 1(-1.675,0) 3(1.675,0)
  round 0.454 hole 0.2 mask+0.05: 2(-0.305,-1.105) 2(-0.305,1.105) 2(0.305,-1.105) 2(0.305,1.105)
  rrect10% 1x1 smd paste+0: 2(0,-0.8) 2(0,0.8)
  body extent -1.7,-0.9 1.7,0.9, height 1.5
NFM31PC#6 [mm]
  rrect10% 0.95x1.2 smd paste+0: 1(-1.675,0) 3(1.675,0)
  round 0.454 hole 0.2 mask+0: 2(-0.305,-1.105) 2(-0.305,1.105) 2(0.305,-1.105) 2(0.305,1.105)
  rrect10% 1x1 smd paste+0: 2(0,-0.8) 2(0,0.8)
  body extent -1.7,-0.9 1.7,0.9, height 1.5
NKD0064A [mm] "QFN, 64-Leads, Body 9x9mm, Pitch 0.5mm"
  rrect40% 0.6x0.25 smd mask+0.07: 1(-4.4,3.75) 2(-4.4,3.25) 3(-4.4,2.75) 4(-4.4,2.25) 5(-4.4,1.75) 6(-4.4,1.25) 7(-4.4,0.75) 8(-4.4,0.25) 9(-4.4,-0.25) 10(-4.4,-0.75) 11(-4.4,-1.25) 12(-4.4,-1.75) 13(-4.4,-2.25) 14(-4.4,-2.75) 15(-4.4,-3.25) 16(-4.4,-3.75) 33(4.4,-3.75) 34(4.4,-3.25) 35(4.4,-2.75) 36(4.4,-2.25) 37(4.4,-1.75) 38(4.4,-1.25) 39(4.4,-0.75) 40(4.4,-0.25) 41(4.4,0.25) 42(4.4,0.75) 43(4.4,1.25) 44(4.4,1.75) 45(4.4,2.25) 46(4.4,2.75) 47(4.4,3.25) 48(4.4,3.75)
  rrect40% 0.25x0.6 smd mask+0.07: 17(-3.75,-4.4) 18(-3.25,-4.4) 19(-2.75,-4.4) 20(-2.25,-4.4) 21(-1.75,-4.4) 22(-1.25,-4.4) 23(-0.75,-4.4) 24(-0.25,-4.4) 25(0.25,-4.4) 26(0.75,-4.4) 27(1.25,-4.4) 28(1.75,-4.4) 29(2.25,-4.4) 30(2.75,-4.4) 31(3.25,-4.4) 32(3.75,-4.4) 49(3.75,4.4) 50(3.25,4.4) 51(2.75,4.4) 52(2.25,4.4) 53(1.75,4.4) 54(1.25,4.4) 55(0.75,4.4) 56(0.25,4.4) 57(-0.25,4.4) 58(-0.75,4.4) 59(-1.25,4.4) 60(-1.75,4.4) 61(-2.25,4.4) 62(-2.75,4.4) 63(-3.25,4.4) 64(-3.75,4.4)
  round 0.454 hole 0.2 mask+0.102: 65(-3.35,-2.04) 65(-3.35,-0.68) 65(-3.35,0.68) 65(-3.35,2.04) 65(-2.04,2.04) 65(-2.04,3.35) 65(-2.04,-0.68) 65(-2.04,0.68) 65(-2.04,-3.35) 65(-2.04,-2.04) 65(-0.68,3.35) 65(-0.68,2.04) 65(-0.68,0.68) 65(-0.68,-0.68) 65(-0.68,-2.04) 65(-0.68,-3.35) 65(0.68,3.35) 65(0.68,2.04) 65(0.68,0.68) 65(0.68,-0.68) 65(0.68,-2.04) 65(0.68,-3.35) 65(2.04,2.04) 65(2.04,3.35) 65(2.04,-0.68) 65(2.04,0.68) 65(2.04,-3.35) 65(2.04,-2.04) 65(3.35,-2.04) 65(3.35,-0.68) 65(3.35,0.68) 65(3.35,2.04)
  rrect1% 7.2x7.2 smd paste-3.6 mask+0.07: 65(0,0)
  silkscreen extent -4.65,-4.65 4.65,4.65, body extent -4.55,-4.55 4.55,4.55, height 0.81
PBC02SAAN [mm] "Sullins 100mil, 1x2, 230 mil above insulator"
  rect 1.65x1.65 hole 1.016: 1(0,1.27)
  round 1.65 hole 1.016: 2(0,-1.27)
  silkscreen extent -1.27,-2.54 1.6,2.54, body extent -1.27,-2.54 1.27,2.54, height 8.38
ProbePoint_TH_40mil [mil]
  round 41 hole 28: 1(0,0)
PS1608G [mm]
  rrect20% 0.45x0.35 smd mask+0.07: 1(0,0.425)
  rrect20% 0.35x0.35 smd mask+0.07: 2(-0.45,-0.425) 3(0.45,-0.425)
  round 0.025 smd paste-1 mask-1: GND(0,0)
  Top Layer region: 1,-0.05 0.075,-0.05 0.075,-0.25 -0.075,-0.25 -0.075,-0.05 -1,-0.05 -1,0.25 -0.525,0.25 -0.525,0.05 0.525,0.05 0.525,0.25 1,0.25
RAPC722X [mm] "Conn_DC Jack"
  oval 1.7x4.3 hole 1.01 slot 3.56 at 90 deg: 1(14.194,0)
  oval 1.5x3.8 hole 0.76 slot 3.05 at 90 deg: 2(7.946,0)
  oval 3.8x1.5 hole 0.76 slot 3.05 at 0 deg: 3(11.197,-4.7)
  silkscreen extent 0.2,-4.57 14.93,4.57, body extent 0.58,-4.97 15.06,4.56, height 10.92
